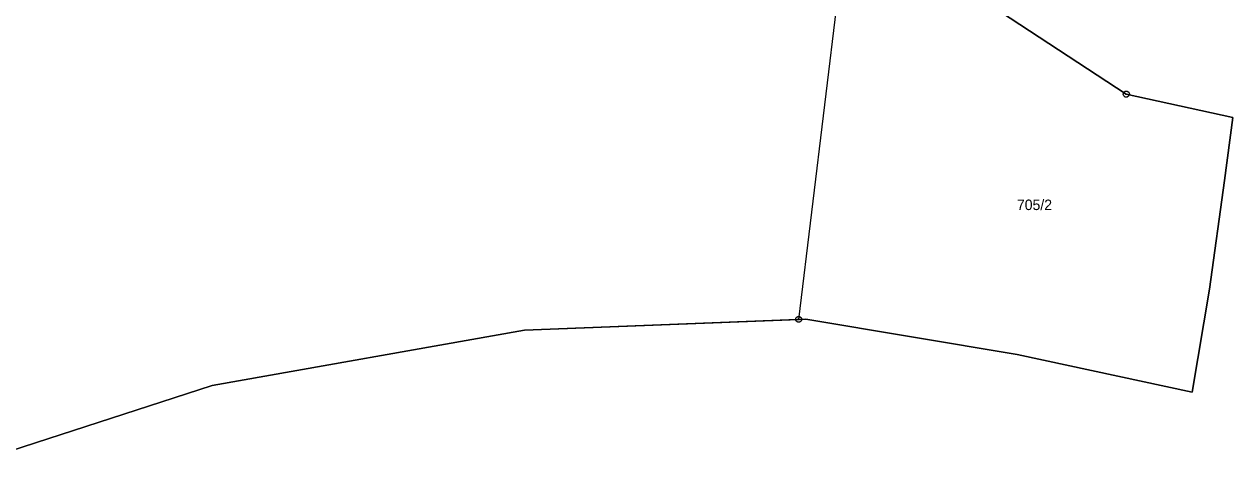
# Model space of a CAD drawing. Extents: x -759699 to -757730, y -1172308 to -1170857.
# Drawn here: x -758156.3 to -757960.4, y -1171143.9 to -1171071.6 of the extents above; entities that cross this region are included whole.
import ezdxf

# ---------------------------------------------------------------- set-up
doc = ezdxf.new("R2010")
doc.units = 0
for name, color, linetype in [('Vrstva 1', 7, 'Continuous'), ('Vrstva 11', 7, 'Continuous'), ('Vrstva 2', 7, 'Continuous'), ('Vrstva 8', 7, 'Continuous')]:
    doc.layers.add(name, color=color, linetype=linetype)

msp = doc.modelspace()

# ---------------------------------------------------------------- linework, layer by layer
at = {"layer": 'Vrstva 1'}
for p, q in [((-758030.77, -1171119.52), (-758022.35, -1171050.03)), ((-757977.68, -1171082.98), (-758001.2, -1171067.51)), ((-757960.42, -1171086.77), (-757977.68, -1171082.98)), ((-757961.76, -1171097), (-757960.42, -1171086.77)), ((-757964.18, -1171114.63), (-757961.76, -1171097)), ((-757966.99, -1171131.32), (-757964.18, -1171114.63)), ((-758075.21, -1171121.26), (-758030.77, -1171119.52)), ((-758030.77, -1171119.52), (-758029.59, -1171119.47)), ((-758029.59, -1171119.47), (-757995.37, -1171125.21)), ((-758125.81, -1171130.25), (-758075.21, -1171121.26)), ((-757995.37, -1171125.21), (-757966.99, -1171131.32)), ((-758168.07, -1171143.92), (-758125.81, -1171130.25))]:
    msp.add_line(p, q, dxfattribs=at)
at = {"layer": 'Vrstva 11'}
for p, q in [((-758001.2, -1171067.51), (-757977.68, -1171082.98)), ((-757977.68, -1171082.98), (-757960.42, -1171086.77)), ((-757960.42, -1171086.77), (-757961.76, -1171097)), ((-757961.76, -1171097), (-757964.18, -1171114.63)), ((-757964.18, -1171114.63), (-757966.99, -1171131.32)), ((-758029.59, -1171119.47), (-758075.21, -1171121.26)), ((-757995.37, -1171125.21), (-758029.59, -1171119.47)), ((-758075.21, -1171121.26), (-758125.81, -1171130.25)), ((-757966.99, -1171131.32), (-757995.37, -1171125.21)), ((-758125.81, -1171130.25), (-758168.07, -1171143.92))]:
    msp.add_line(p, q, dxfattribs=at)
at = {"layer": 'Vrstva 8'}
for p, q in [((-757977.8, -1171082.98), (-757977.56, -1171082.98)), ((-758030.89, -1171119.52), (-758030.65, -1171119.52))]:
    msp.add_line(p, q, dxfattribs=at)
for points in [[(-757977.53, -1171082.5), (-757977.28, -1171082.68), (-757977.18, -1171082.97), (-757977.28, -1171083.26), (-757977.53, -1171083.44), (-757977.84, -1171083.44), (-757978.09, -1171083.26), (-757978.19, -1171082.97), (-757978.09, -1171082.68), (-757977.84, -1171082.5)], [(-758030.62, -1171119.04), (-758030.37, -1171119.22), (-758030.27, -1171119.51), (-758030.37, -1171119.8), (-758030.62, -1171119.98), (-758030.93, -1171119.98), (-758031.18, -1171119.8), (-758031.28, -1171119.51), (-758031.18, -1171119.22), (-758030.93, -1171119.04)]]:
    msp.add_lwpolyline(points, close=True, dxfattribs=at)

# ---------------------------------------------------------------- texts
at = {"layer": 'Vrstva 2'}
msp.add_text('705/2', height=1.7, dxfattribs=at).set_placement((-757995.403, -1171101.78))

doc.saveas('drawing.dxf')
